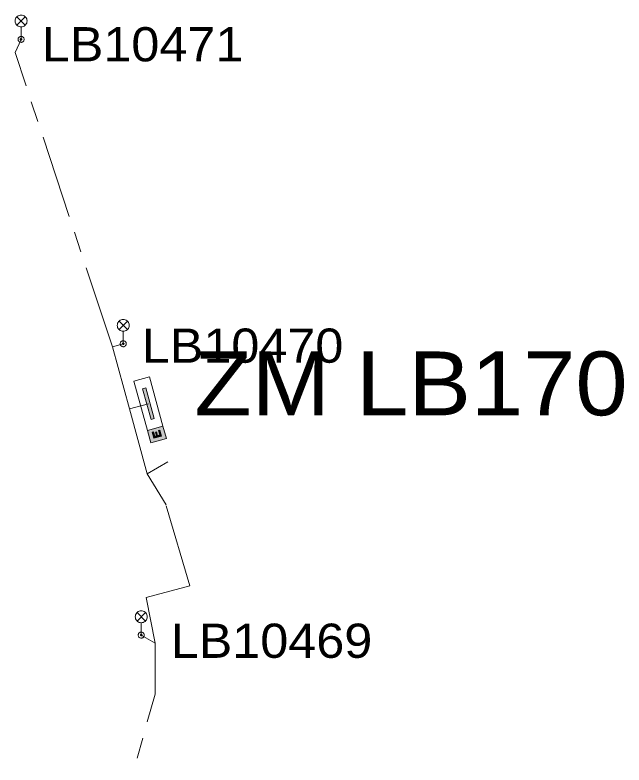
# Model space of a CAD drawing. Extents: x -691843 to -691118, y -976392 to -975793.
# Drawn here: x -691763.31 to -691725.16, y -976332.04 to -976285.05 of the extents above; entities that cross this region are included whole.
import ezdxf

# ---------------------------------------------------------------- set-up
doc = ezdxf.new("R2010")
doc.units = 0
doc.header["$LTSCALE"] = 0.87
doc.linetypes.add('LONG_DASH_SHORT_DASH', pattern=[9.9, 6, -1.2, 1.5, -1.2])
doc.layers.add('1', color=7, linetype='Continuous', lineweight=13)

msp = doc.modelspace()

# ---------------------------------------------------------------- hatches: boundary and pattern name
at = {"layer": '1'}
for points in [[(-691754.78, -976310.39), (-691755.313, -976308.463), (-691755.121, -976308.409), (-691754.587, -976310.337)], [(-691754.792, -976311.846), (-691755.005, -976311.075), (-691754.041, -976310.808), (-691753.828, -976311.579)], [(-691754.128, -976311.432), (-691754.61, -976311.565), (-691754.713, -976311.193), (-691754.633, -976311.171), (-691754.561, -976311.433), (-691754.455, -976311.404), (-691754.517, -976311.177), (-691754.438, -976311.154), (-691754.375, -976311.382), (-691754.246, -976311.346), (-691754.319, -976311.084), (-691754.231, -976311.06)]]:
    msp.add_hatch(color=256, dxfattribs=at).paths.add_polyline_path(points)

# ---------------------------------------------------------------- linework, layer by layer
for p, q in [((-691763.195, -976285.155), (-691762.665, -976285.685)), ((-691763.195, -976285.685), (-691762.665, -976285.155)), ((-691762.93, -976286.57), (-691762.93, -976285.795)), ((-691756.795, -976304.225), (-691756.265, -976304.755)), ((-691756.795, -976304.755), (-691756.265, -976304.225)), ((-691756.53, -976305.64), (-691756.53, -976304.865)), ((-691755.665, -976322.485), (-691755.135, -976323.015)), ((-691755.665, -976323.015), (-691755.135, -976322.485)), ((-691755.4, -976323.9), (-691755.4, -976323.125))]:
    msp.add_line(p, q, dxfattribs=at)
at = {"layer": '1', "linetype": 'LONG_DASH_SHORT_DASH'}
for p, q in [((-691763.31, -976287.4), (-691762.93, -976286.57)), ((-691763.31, -976287.4), (-691762.93, -976286.57)), ((-691763.31, -976287.4), (-691762.93, -976286.57)), ((-691763.31, -976287.4), (-691762.93, -976286.57)), ((-691763.31, -976287.4), (-691762.93, -976286.57)), ((-691763.31, -976287.4), (-691762.93, -976286.57)), ((-691763.31, -976287.4), (-691762.93, -976286.57)), ((-691763.31, -976287.4), (-691762.93, -976286.57)), ((-691757.21, -976305.84), (-691756.53, -976305.64)), ((-691757.21, -976305.84), (-691756.53, -976305.64)), ((-691757.21, -976305.84), (-691756.53, -976305.64)), ((-691757.21, -976305.84), (-691756.53, -976305.64)), ((-691757.21, -976305.84), (-691756.53, -976305.64)), ((-691757.21, -976305.84), (-691756.53, -976305.64)), ((-691757.21, -976305.84), (-691756.53, -976305.64)), ((-691757.21, -976305.84), (-691756.53, -976305.64)), ((-691756.145, -976309.727), (-691754.95, -976309.4)), ((-691756.145, -976309.727), (-691754.95, -976309.4)), ((-691756.145, -976309.727), (-691754.95, -976309.4)), ((-691756.145, -976309.727), (-691754.95, -976309.4)), ((-691756.145, -976309.727), (-691754.95, -976309.4)), ((-691756.145, -976309.727), (-691754.95, -976309.4)), ((-691756.145, -976309.727), (-691754.95, -976309.4)), ((-691756.145, -976309.727), (-691754.95, -976309.4)), ((-691755.03, -976313.8), (-691753.731, -976313.05)), ((-691755.03, -976313.8), (-691753.731, -976313.05)), ((-691755.03, -976313.8), (-691753.731, -976313.05)), ((-691755.03, -976313.8), (-691753.731, -976313.05)), ((-691755.03, -976313.8), (-691753.731, -976313.05)), ((-691755.03, -976313.8), (-691753.731, -976313.05)), ((-691755.03, -976313.8), (-691753.731, -976313.05)), ((-691753.85, -976315.74), (-691755.03, -976313.8)), ((-691753.85, -976315.74), (-691755.03, -976313.8)), ((-691753.85, -976315.74), (-691755.03, -976313.8)), ((-691753.85, -976315.74), (-691755.03, -976313.8)), ((-691753.85, -976315.74), (-691755.03, -976313.8)), ((-691753.85, -976315.74), (-691755.03, -976313.8)), ((-691753.85, -976315.74), (-691755.03, -976313.8)), ((-691754.53, -976324.41), (-691755.4, -976323.9)), ((-691754.53, -976324.41), (-691755.4, -976323.9)), ((-691754.53, -976324.41), (-691755.4, -976323.9)), ((-691754.53, -976324.41), (-691755.4, -976323.9)), ((-691754.53, -976324.41), (-691755.4, -976323.9)), ((-691754.53, -976324.41), (-691755.4, -976323.9)), ((-691754.53, -976324.41), (-691755.4, -976323.9)), ((-691754.53, -976324.41), (-691755.4, -976323.9))]:
    msp.add_line(p, q, dxfattribs=at)
at = {"layer": '1'}
for points in [[(-691762.555, -976285.42), (-691762.561, -976285.355), (-691762.578, -976285.292), (-691762.605, -976285.232), (-691762.643, -976285.179), (-691762.689, -976285.133), (-691762.742, -976285.095), (-691762.802, -976285.068), (-691762.865, -976285.051), (-691762.93, -976285.045), (-691762.995, -976285.051), (-691763.058, -976285.068), (-691763.118, -976285.095), (-691763.171, -976285.133), (-691763.217, -976285.179), (-691763.255, -976285.232), (-691763.282, -976285.292), (-691763.299, -976285.355), (-691763.305, -976285.42), (-691763.299, -976285.485), (-691763.282, -976285.548), (-691763.255, -976285.607), (-691763.217, -976285.661), (-691763.171, -976285.707), (-691763.118, -976285.745), (-691763.058, -976285.772), (-691762.995, -976285.789), (-691762.93, -976285.795), (-691762.865, -976285.789), (-691762.802, -976285.772), (-691762.742, -976285.745), (-691762.689, -976285.707), (-691762.643, -976285.661), (-691762.605, -976285.607), (-691762.578, -976285.548), (-691762.561, -976285.485)], [(-691762.74, -976286.57), (-691762.743, -976286.537), (-691762.751, -976286.505), (-691762.765, -976286.475), (-691762.784, -976286.448), (-691762.808, -976286.424), (-691762.835, -976286.405), (-691762.865, -976286.391), (-691762.897, -976286.383), (-691762.93, -976286.38), (-691762.963, -976286.383), (-691762.995, -976286.391), (-691763.025, -976286.405), (-691763.052, -976286.424), (-691763.076, -976286.448), (-691763.095, -976286.475), (-691763.109, -976286.505), (-691763.117, -976286.537), (-691763.12, -976286.57), (-691763.117, -976286.603), (-691763.109, -976286.635), (-691763.095, -976286.665), (-691763.076, -976286.692), (-691763.052, -976286.716), (-691763.025, -976286.735), (-691762.995, -976286.749), (-691762.963, -976286.757), (-691762.93, -976286.76), (-691762.897, -976286.757), (-691762.865, -976286.749), (-691762.835, -976286.735), (-691762.808, -976286.716), (-691762.784, -976286.692), (-691762.765, -976286.665), (-691762.751, -976286.635), (-691762.743, -976286.603)], [(-691762.88, -976286.57), (-691762.881, -976286.561), (-691762.883, -976286.553), (-691762.887, -976286.545), (-691762.892, -976286.538), (-691762.898, -976286.532), (-691762.905, -976286.527), (-691762.913, -976286.523), (-691762.921, -976286.521), (-691762.93, -976286.52), (-691762.939, -976286.521), (-691762.947, -976286.523), (-691762.955, -976286.527), (-691762.962, -976286.532), (-691762.968, -976286.538), (-691762.973, -976286.545), (-691762.977, -976286.553), (-691762.979, -976286.561), (-691762.98, -976286.57), (-691762.979, -976286.579), (-691762.977, -976286.587), (-691762.973, -976286.595), (-691762.968, -976286.602), (-691762.962, -976286.608), (-691762.955, -976286.613), (-691762.947, -976286.617), (-691762.939, -976286.619), (-691762.93, -976286.62), (-691762.921, -976286.619), (-691762.913, -976286.617), (-691762.905, -976286.613), (-691762.898, -976286.608), (-691762.892, -976286.602), (-691762.887, -976286.595), (-691762.883, -976286.587), (-691762.881, -976286.579)], [(-691756.155, -976304.49), (-691756.161, -976304.425), (-691756.178, -976304.362), (-691756.205, -976304.302), (-691756.243, -976304.249), (-691756.289, -976304.203), (-691756.342, -976304.165), (-691756.402, -976304.138), (-691756.465, -976304.121), (-691756.53, -976304.115), (-691756.595, -976304.121), (-691756.658, -976304.138), (-691756.718, -976304.165), (-691756.771, -976304.203), (-691756.817, -976304.249), (-691756.855, -976304.302), (-691756.882, -976304.362), (-691756.899, -976304.425), (-691756.905, -976304.49), (-691756.899, -976304.555), (-691756.882, -976304.618), (-691756.855, -976304.678), (-691756.817, -976304.731), (-691756.771, -976304.777), (-691756.718, -976304.815), (-691756.658, -976304.842), (-691756.595, -976304.859), (-691756.53, -976304.865), (-691756.465, -976304.859), (-691756.402, -976304.842), (-691756.342, -976304.815), (-691756.289, -976304.777), (-691756.243, -976304.731), (-691756.205, -976304.678), (-691756.178, -976304.618), (-691756.161, -976304.555)], [(-691756.34, -976305.64), (-691756.343, -976305.607), (-691756.351, -976305.575), (-691756.365, -976305.545), (-691756.384, -976305.518), (-691756.408, -976305.494), (-691756.435, -976305.475), (-691756.465, -976305.461), (-691756.497, -976305.453), (-691756.53, -976305.45), (-691756.563, -976305.453), (-691756.595, -976305.461), (-691756.625, -976305.475), (-691756.652, -976305.494), (-691756.676, -976305.518), (-691756.695, -976305.545), (-691756.709, -976305.575), (-691756.717, -976305.607), (-691756.72, -976305.64), (-691756.717, -976305.673), (-691756.709, -976305.705), (-691756.695, -976305.735), (-691756.676, -976305.762), (-691756.652, -976305.786), (-691756.625, -976305.805), (-691756.595, -976305.819), (-691756.563, -976305.827), (-691756.53, -976305.83), (-691756.497, -976305.827), (-691756.465, -976305.819), (-691756.435, -976305.805), (-691756.408, -976305.786), (-691756.384, -976305.762), (-691756.365, -976305.735), (-691756.351, -976305.705), (-691756.343, -976305.673)], [(-691756.48, -976305.64), (-691756.481, -976305.631), (-691756.483, -976305.623), (-691756.487, -976305.615), (-691756.492, -976305.608), (-691756.498, -976305.602), (-691756.505, -976305.597), (-691756.513, -976305.593), (-691756.521, -976305.591), (-691756.53, -976305.59), (-691756.539, -976305.591), (-691756.547, -976305.593), (-691756.555, -976305.597), (-691756.562, -976305.602), (-691756.568, -976305.608), (-691756.573, -976305.615), (-691756.577, -976305.623), (-691756.579, -976305.631), (-691756.58, -976305.64), (-691756.579, -976305.649), (-691756.577, -976305.657), (-691756.573, -976305.665), (-691756.568, -976305.672), (-691756.562, -976305.678), (-691756.555, -976305.683), (-691756.547, -976305.687), (-691756.539, -976305.689), (-691756.53, -976305.69), (-691756.521, -976305.689), (-691756.513, -976305.687), (-691756.505, -976305.683), (-691756.498, -976305.678), (-691756.492, -976305.672), (-691756.487, -976305.665), (-691756.483, -976305.657), (-691756.481, -976305.649)], [(-691754.78, -976310.39), (-691755.313, -976308.463), (-691755.121, -976308.409), (-691754.587, -976310.337)], [(-691754.792, -976311.846), (-691755.005, -976311.075), (-691754.041, -976310.808), (-691753.828, -976311.579)], [(-691754.792, -976311.846), (-691755.005, -976311.075), (-691754.041, -976310.808), (-691753.828, -976311.579)], [(-691754.128, -976311.432), (-691754.61, -976311.565), (-691754.713, -976311.193), (-691754.633, -976311.171), (-691754.561, -976311.433), (-691754.455, -976311.404), (-691754.517, -976311.177), (-691754.438, -976311.154), (-691754.375, -976311.382), (-691754.246, -976311.346), (-691754.319, -976311.084), (-691754.231, -976311.06)], [(-691755.025, -976322.75), (-691755.031, -976322.685), (-691755.048, -976322.622), (-691755.075, -976322.562), (-691755.113, -976322.509), (-691755.159, -976322.463), (-691755.212, -976322.425), (-691755.272, -976322.398), (-691755.335, -976322.381), (-691755.4, -976322.375), (-691755.465, -976322.381), (-691755.528, -976322.398), (-691755.588, -976322.425), (-691755.641, -976322.463), (-691755.687, -976322.509), (-691755.725, -976322.562), (-691755.752, -976322.622), (-691755.769, -976322.685), (-691755.775, -976322.75), (-691755.769, -976322.815), (-691755.752, -976322.878), (-691755.725, -976322.938), (-691755.687, -976322.991), (-691755.641, -976323.037), (-691755.588, -976323.075), (-691755.528, -976323.102), (-691755.465, -976323.119), (-691755.4, -976323.125), (-691755.335, -976323.119), (-691755.272, -976323.102), (-691755.212, -976323.075), (-691755.159, -976323.037), (-691755.113, -976322.991), (-691755.075, -976322.938), (-691755.048, -976322.878), (-691755.031, -976322.815)], [(-691755.21, -976323.9), (-691755.213, -976323.867), (-691755.221, -976323.835), (-691755.235, -976323.805), (-691755.254, -976323.778), (-691755.278, -976323.754), (-691755.305, -976323.735), (-691755.335, -976323.721), (-691755.367, -976323.713), (-691755.4, -976323.71), (-691755.433, -976323.713), (-691755.465, -976323.721), (-691755.495, -976323.735), (-691755.522, -976323.754), (-691755.546, -976323.778), (-691755.565, -976323.805), (-691755.579, -976323.835), (-691755.587, -976323.867), (-691755.59, -976323.9), (-691755.587, -976323.933), (-691755.579, -976323.965), (-691755.565, -976323.995), (-691755.546, -976324.022), (-691755.522, -976324.046), (-691755.495, -976324.065), (-691755.465, -976324.079), (-691755.433, -976324.087), (-691755.4, -976324.09), (-691755.367, -976324.087), (-691755.335, -976324.079), (-691755.305, -976324.065), (-691755.278, -976324.046), (-691755.254, -976324.022), (-691755.235, -976323.995), (-691755.221, -976323.965), (-691755.213, -976323.933)], [(-691755.35, -976323.9), (-691755.351, -976323.891), (-691755.353, -976323.883), (-691755.357, -976323.875), (-691755.362, -976323.868), (-691755.368, -976323.862), (-691755.375, -976323.857), (-691755.383, -976323.853), (-691755.391, -976323.851), (-691755.4, -976323.85), (-691755.409, -976323.851), (-691755.417, -976323.853), (-691755.425, -976323.857), (-691755.432, -976323.862), (-691755.438, -976323.868), (-691755.443, -976323.875), (-691755.447, -976323.883), (-691755.449, -976323.891), (-691755.45, -976323.9), (-691755.449, -976323.909), (-691755.447, -976323.917), (-691755.443, -976323.925), (-691755.438, -976323.932), (-691755.432, -976323.938), (-691755.425, -976323.943), (-691755.417, -976323.947), (-691755.409, -976323.949), (-691755.4, -976323.95), (-691755.391, -976323.949), (-691755.383, -976323.947), (-691755.375, -976323.943), (-691755.368, -976323.938), (-691755.362, -976323.932), (-691755.357, -976323.925), (-691755.353, -976323.917), (-691755.351, -976323.909)]]:
    msp.add_lwpolyline(points, close=True, dxfattribs=at)
at = {"layer": '1', "linetype": 'LONG_DASH_SHORT_DASH'}
for points in [[(-691755.03, -976313.8), (-691756.145, -976309.727), (-691757.21, -976305.84), (-691763.31, -976287.4)], [(-691755.03, -976313.8), (-691756.145, -976309.727), (-691757.21, -976305.84), (-691763.31, -976287.4)], [(-691755.03, -976313.8), (-691756.145, -976309.727), (-691757.21, -976305.84), (-691763.31, -976287.4)], [(-691755.03, -976313.8), (-691756.145, -976309.727), (-691757.21, -976305.84), (-691763.31, -976287.4)], [(-691755.03, -976313.8), (-691756.145, -976309.727), (-691757.21, -976305.84), (-691763.31, -976287.4)], [(-691755.03, -976313.8), (-691756.145, -976309.727), (-691757.21, -976305.84), (-691763.31, -976287.4)], [(-691755.03, -976313.8), (-691756.145, -976309.727), (-691757.21, -976305.84), (-691763.31, -976287.4)], [(-691755.03, -976313.8), (-691756.145, -976309.727), (-691757.21, -976305.84), (-691763.31, -976287.4)], [(-691753.85, -976315.74), (-691755.03, -976313.8), (-691753.731, -976313.05)], [(-691757.43, -976337.91), (-691757.33, -976337.64), (-691754.54, -976327.6), (-691754.53, -976324.41), (-691755.09, -976321.54), (-691752.36, -976320.81), (-691753.85, -976315.74)], [(-691757.43, -976337.91), (-691757.33, -976337.64), (-691754.54, -976327.6), (-691754.53, -976324.41), (-691755.09, -976321.54), (-691752.36, -976320.81), (-691753.85, -976315.74)], [(-691757.43, -976337.91), (-691757.33, -976337.64), (-691754.54, -976327.6), (-691754.53, -976324.41), (-691755.09, -976321.54), (-691752.36, -976320.81), (-691753.85, -976315.74)], [(-691757.43, -976337.91), (-691757.33, -976337.64), (-691754.54, -976327.6), (-691754.53, -976324.41), (-691755.09, -976321.54), (-691752.36, -976320.81), (-691753.85, -976315.74)], [(-691757.43, -976337.91), (-691757.33, -976337.64), (-691754.54, -976327.6), (-691754.53, -976324.41), (-691755.09, -976321.54), (-691752.36, -976320.81), (-691753.85, -976315.74)], [(-691757.43, -976337.91), (-691757.33, -976337.64), (-691754.54, -976327.6), (-691754.53, -976324.41), (-691755.09, -976321.54), (-691752.36, -976320.81), (-691753.85, -976315.74)], [(-691757.43, -976337.91), (-691757.33, -976337.64), (-691754.54, -976327.6), (-691754.53, -976324.41), (-691755.09, -976321.54), (-691752.36, -976320.81), (-691753.85, -976315.74)], [(-691757.43, -976337.91), (-691757.33, -976337.64), (-691754.54, -976327.6), (-691754.53, -976324.41), (-691755.09, -976321.54), (-691752.36, -976320.81), (-691753.85, -976315.74)]]:
    msp.add_lwpolyline(points, dxfattribs=at)
at = {"layer": '1'}
msp.add_lwpolyline([(-691755.005, -976311.075), (-691755.859, -976307.991), (-691754.895, -976307.724), (-691754.041, -976310.808)], dxfattribs=at)

# ---------------------------------------------------------------- texts
at = {"layer": '1', "width": 1.1}
for s, height, p in [('LB10471', 2.144, (-691761.633, -976287.95)), ('LB10470', 2.144, (-691755.369, -976306.833)), ('ZM LB170', 4, (-691752.075, -976310.128)), ('LB10469', 2.144, (-691753.556, -976325.324))]:
    msp.add_text(s, height=height, dxfattribs=at).set_placement(p)

doc.saveas('drawing.dxf')
